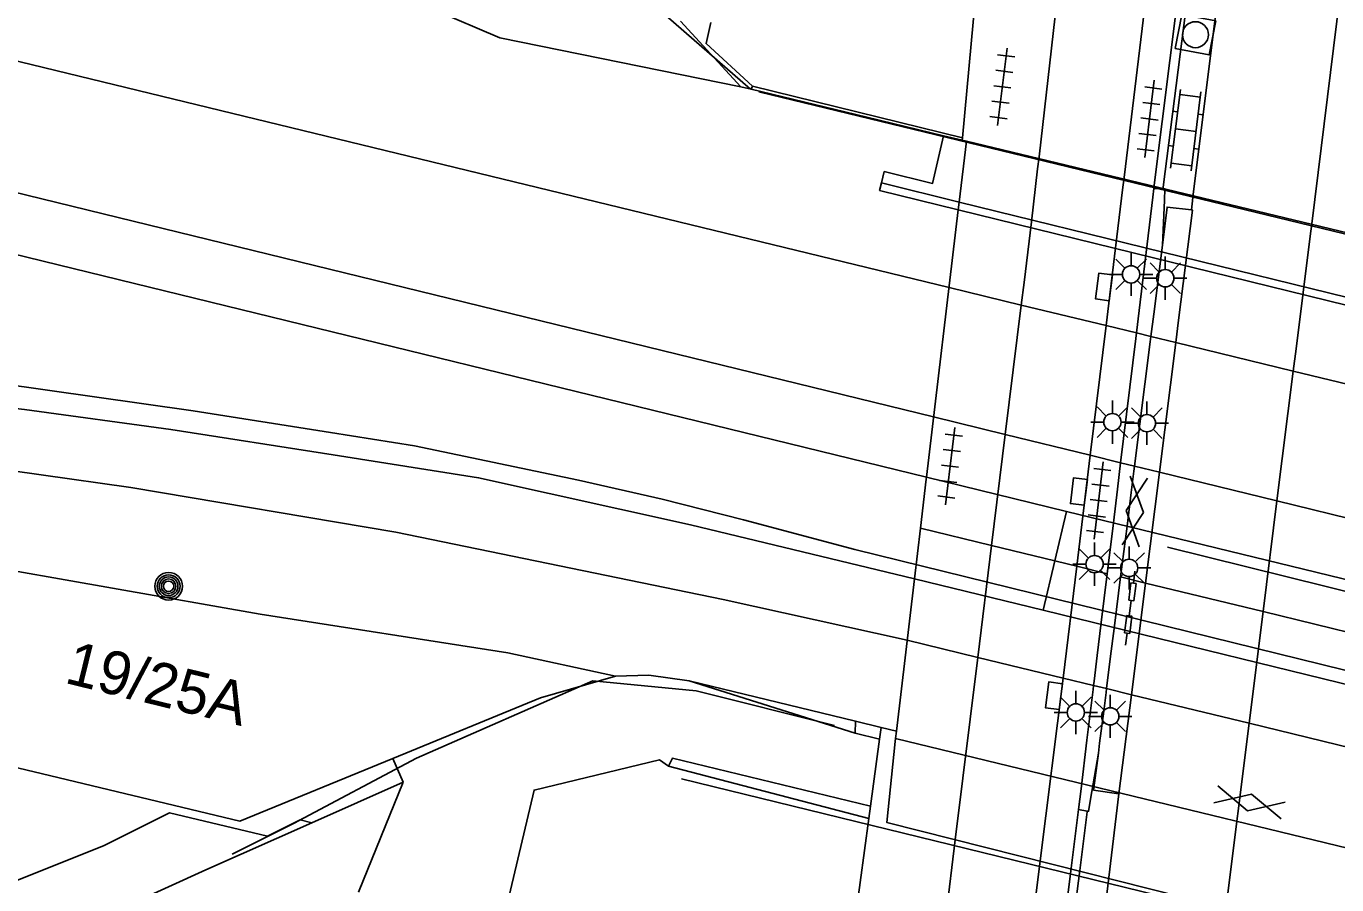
# Model space of a CAD drawing. Extents: x 131000 to 133014, y 396499 to 399001.
# Drawn here: x 131662.22 to 131700.07, y 397388.52 to 397413.33 of the extents above; entities that cross this region are included whole.
import ezdxf

# ---------------------------------------------------------------- set-up
doc = ezdxf.new("R2010")
doc.units = 0
for name, color, linetype in [('gg-afsc-hekwerk', 7, 'Continuous'), ('gg-afsc-muur', 7, 'Continuous'), ('gg-aspt-spoorlijn', 7, 'Continuous'), ('gg-knt-BGT kruinlijn', 7, 'Continuous'), ('gg-knt-bronhoudergrens niveau 01', 7, 'Continuous'), ('gg-knt-verharding', 7, 'Continuous'), ('gg-knt-verharding niveau 01', 7, 'Continuous'), ('gg-knt-verharding nz', 7, 'Continuous'), ('gg-kntw-beschoeiing', 7, 'Continuous'), ('gg-kwrk-kunstwerk', 7, 'Continuous'), ('gg-kwrk-kunstwerk niveau 01', 7, 'Continuous'), ('gt-anno-nummer portaalmast', 7, 'Continuous'), ('gt-grn-afwateringsgoot', 7, 'Continuous'), ('gt-grn-bladgrens', 7, 'Continuous'), ('gt-grn-groengrens', 7, 'Continuous'), ('gt-grn-weggrens', 7, 'Continuous'), ('gt-symb-afwateringsgoot', 7, 'Continuous'), ('gt-symb-gesloten verharding', 7, 'Continuous'), ('gt-symb-klinker verharding', 7, 'Continuous'), ('gt-symb-kolk', 7, 'Continuous'), ('gt-symb-lichtmast', 7, 'Continuous'), ('gt-symb-portaalmast', 7, 'Continuous'), ('gt-symb-rioolschacht', 7, 'Continuous'), ('gt-symb-tegel verharding', 7, 'Continuous'), ('gx-grn-maaiveld', 7, 'Continuous'), ('gx-knt-lijn weginrichtingselement', 7, 'Continuous')]:
    doc.layers.add(name, color=color, linetype=linetype)

# ---------------------------------------------------------------- blocks, each defined once
blk = doc.blocks.new('gt0-TEG1')
at = {"layer": 'gt-symb-tegel verharding'}
for p, q in [((-1.125, 0), (1.125, 0)), ((-0.9, -0.25), (-0.9, 0.25)), ((-0.45, -0.25), (-0.45, 0.25)), ((0, -0.25), (0, 0.25)), ((0.45, -0.25), (0.45, 0.25)), ((0.9, -0.25), (0.9, 0.25))]:
    blk.add_line(p, q, dxfattribs=at)
blk = doc.blocks.new('gt0-KOLK')
at = {"layer": 'gt-symb-kolk'}
blk.add_lwpolyline([(0, 0), (0.375, 0), (0.375, 0.4), (-0.375, 0.4), (-0.375, 0), (0, 0)], dxfattribs=at)
blk = doc.blocks.new('gt0-LMAST')
at = {"layer": 'gt-symb-lichtmast'}
for p, q in [((-0.182, 0.173), (-0.447, 0.438)), ((-0.005, 0.246), (-0.005, 0.621)), ((0.172, 0.173), (0.437, 0.438)), ((-0.255, -0.004), (-0.63, -0.004)), ((-0.182, -0.181), (-0.447, -0.446)), ((-0.005, -0.254), (-0.005, -0.629)), ((0.437, -0.446), (0.172, -0.181)), ((0.245, -0.004), (0.62, -0.004))]:
    blk.add_line(p, q, dxfattribs=at)
blk.add_circle((-0.005, -0.004), 0.25, dxfattribs=at)
blk = doc.blocks.new('gt0-KL1')
at = {"layer": 'gt-symb-klinker verharding'}
for p, q in [((-0.5, 0.3), (-0.5, 0.45)), ((0.5, 0.3), (0.5, 0.45)), ((-1.15, 0.3), (1.15, 0.3)), ((-1, -0.3), (-1, 0.3)), ((0, -0.3), (0, 0.3)), ((1, -0.3), (1, 0.3)), ((-1.15, -0.3), (1.15, -0.3)), ((-0.5, -0.45), (-0.5, -0.3)), ((0.5, -0.45), (0.5, -0.3))]:
    blk.add_line(p, q, dxfattribs=at)
blk = doc.blocks.new('gt0-RS')
at = {"layer": 'gt-symb-rioolschacht'}
blk.add_lwpolyline([(-0.5, -0.5), (0.5, -0.5), (0.5, 0.5), (-0.5, 0.5)], close=True, dxfattribs=at)
blk.add_circle((0, 0), 0.375, dxfattribs=at)
blk = doc.blocks.new('gt0-AFWGT_1')
at = {"layer": 'gt-symb-afwateringsgoot'}
for p, q in [((-1.076, 0), (-0.726, 0)), ((-0.225, 0), (0.225, 0)), ((0.725, 0), (1.075, 0))]:
    blk.add_line(p, q, dxfattribs=at)
for points in [[(-0.726, 0.075), (-0.225, 0.075), (-0.225, -0.075), (-0.726, -0.075)], [(0.225, 0.075), (0.725, 0.075), (0.725, -0.075), (0.225, -0.075)]]:
    blk.add_lwpolyline(points, close=True, dxfattribs=at)
blk = doc.blocks.new('gt0-GESVH1')
at = {"layer": 'gt-symb-gesloten verharding'}
for p, q in [((-0.992, -0.261), (0.008, 0.239)), ((0.008, -0.261), (-0.992, 0.239)), ((0.008, 0.239), (1.008, -0.261)), ((1.008, 0.239), (0.008, -0.261))]:
    blk.add_line(p, q, dxfattribs=at)
blk = doc.blocks.new('gt0-PORTM')
at = {"layer": 'gt-symb-portaalmast'}
for radius in [0.4, 0.33, 0.27, 0.21, 0.15]:
    blk.add_circle((0, 0), radius, dxfattribs=at)

msp = doc.modelspace()

# ---------------------------------------------------------------- linework, layer by layer
at = {"layer": 'gg-afsc-hekwerk'}
for p, q in [((131681.36, 397394.418), (131686.156, 397392.9)), ((131681.36, 397394.418), (131686.167, 397393.246)), ((131686.167, 397393.246), (131686.909, 397393.066)), ((131686.156, 397392.9), (131686.862, 397392.726)), ((131686.909, 397393.066), (131687.346, 397392.959))]:
    msp.add_line(p, q, dxfattribs=at)
for points in [[(131000, 397578.954), (131023.909, 397573.075), (131026.424, 397572.808), (131028.848, 397572.282), (131031.154, 397571.32), (131074.945, 397560.582), (131075.617, 397563.17), (131129.246, 397549.781), (131134.14, 397548.559), (131160.34, 397542.075), (131253.589, 397518.947), (131281.644, 397511.969), (131366.85, 397490.76), (131408.241, 397480.462), (131415.53, 397478.732), (131442.327, 397472.075), (131471.538, 397464.853), (131483.734, 397461.851), (131495.913, 397458.862), (131510.417, 397455.392), (131520.022, 397452.992), (131680.243, 397414.026), (131683.133, 397411.511)], [(131615.544, 397410.102), (131620.261, 397409.009), (131622.612, 397408.496), (131624.978, 397407.98), (131629.886, 397407.06), (131634.678, 397406.22), (131637.064, 397405.839), (131639.453, 397405.498), (131644.286, 397404.898), (131649.239, 397404.372), (131654.019, 397403.86), (131658.97, 397403.278), (131661.391, 397403.013), (131667.033, 397402.217), (131671.003, 397401.595), (131673.429, 397401.203), (131678.166, 397400.215), (131680.583, 397399.662), (131682.932, 397399.07), (131686.144, 397398.212)], [(131611.339, 397404.05), (131668.384, 397390.361), (131672.799, 397392.172)], [(131668.166, 397389.409), (131669.936, 397390.288), (131673.487, 397392.183), (131678.576, 397394.412), (131681.563, 397394.125), (131685.563, 397393.129)], [(131672.799, 397392.172), (131677.071, 397393.925), (131679.238, 397394.55)], [(131679.238, 397394.55), (131680.193, 397394.583), (131681.36, 397394.418)]]:
    msp.add_lwpolyline(points, dxfattribs=at)
at = {"layer": 'gg-afsc-muur'}
for p, q in [((131694.796, 397408.742), (131696.097, 397419.11)), ((131696.38, 397419.146), (131695.051, 397408.68)), ((131694.784, 397408.646), (131694.796, 397408.742)), ((131694.753, 397408.39), (131694.357, 397405.116)), ((131694.784, 397408.646), (131694.753, 397408.39)), ((131695.045, 397408.635), (131694.784, 397408.646)), ((131695.051, 397408.68), (131695.045, 397408.635)), ((131694.357, 397405.116), (131694.278, 397404.468)), ((131694.259, 397404.311), (131693.824, 397400.72)), ((131694.278, 397404.468), (131694.259, 397404.311)), ((131693.824, 397400.72), (131693.732, 397399.958)), ((131693.732, 397399.958), (131693.613, 397398.979)), ((131693.613, 397398.979), (131693.435, 397397.511)), ((131693.435, 397397.511), (131693.264, 397396.101)), ((131693.264, 397396.101), (131693.148, 397395.145)), ((131693.148, 397395.145), (131693.059, 397394.409)), ((131693.059, 397394.409), (131693.043, 397394.279)), ((131693.03, 397394.168), (131692.965, 397393.629)), ((131693.043, 397394.279), (131693.03, 397394.168)), ((131692.965, 397393.629), (131692.852, 397392.699)), ((131692.852, 397392.699), (131692.681, 397391.293)), ((131692.681, 397391.293), (131692.609, 397390.693)), ((131692.609, 397390.693), (131692.397, 397388.998)), ((131692.853, 397390.632), (131692.641, 397388.938)), ((131692.853, 397390.632), (131692.855, 397390.651)), ((131692.641, 397388.938), (131684.58, 397324.435))]:
    msp.add_line(p, q, dxfattribs=at)
msp.add_lwpolyline([(131692.397, 397388.998), (131684.363, 397324.714), (131683.678, 397324.799), (131683.647, 397324.551)], dxfattribs=at)
at = {"layer": 'gg-aspt-spoorlijn'}
for p, q in [((131688.867, 397405.783), (131690.954, 397405.276)), ((131690.954, 397405.276), (131693.404, 397404.681)), ((131693.404, 397404.681), (131694.278, 397404.468)), ((131694.278, 397404.468), (131694.7, 397404.366)), ((131694.7, 397404.366), (131695.417, 397404.192)), ((131695.417, 397404.192), (131698.809, 397403.367)), ((131698.809, 397403.367), (131702.237, 397402.535)), ((131688.423, 397402.041), (131690.492, 397401.535)), ((131690.492, 397401.535), (131692.947, 397400.934)), ((131692.947, 397400.934), (131693.824, 397400.72)), ((131693.824, 397400.72), (131694.227, 397400.621)), ((131694.227, 397400.621), (131694.945, 397400.445)), ((131694.945, 397400.445), (131698.338, 397399.615)), ((131698.338, 397399.615), (131701.77, 397398.775)), ((131687.658, 397395.589), (131689.697, 397395.093)), ((131689.697, 397395.093), (131692.162, 397394.494)), ((131692.162, 397394.494), (131693.043, 397394.279)), ((131693.043, 397394.279), (131693.416, 397394.189)), ((131693.416, 397394.189), (131694.136, 397394.014)), ((131694.136, 397394.014), (131697.533, 397393.187)), ((131697.533, 397393.187), (131700.973, 397392.351))]:
    msp.add_line(p, q, dxfattribs=at)
for points in [[(131000, 397574.063), (131015.158, 397570.378), (131155.057, 397536.094), (131235.084, 397516.609), (131444.076, 397465.45), (131583.687, 397431.335), (131688.867, 397405.783)], [(131000, 397570.437), (131010.144, 397567.969), (131268.679, 397504.671), (131357.363, 397483.039), (131688.423, 397402.041)], [(131687.658, 397395.589), (131682.349, 397396.764), (131672.888, 397398.708), (131665.233, 397400.005), (131657.459, 397401.104), (131644.632, 397402.561), (131637.954, 397403.425), (131633.845, 397404.09), (131626.094, 397405.478), (131616.553, 397407.522), (131608.371, 397409.522), (131568.382, 397419.291), (131463.389, 397444.974), (131387.923, 397463.502)]]:
    msp.add_lwpolyline(points, dxfattribs=at)
at = {"layer": 'gg-knt-BGT kruinlijn'}
msp.add_lwpolyline([(131683.19, 397411.6), (131681.85, 397412.83), (131681.991, 397413.439)], dxfattribs=at)
at = {"layer": 'gg-knt-bronhoudergrens niveau 01'}
msp.add_line((131718.733, 397402.927), (131689.368, 397410.01), dxfattribs=at)
at = {"layer": 'gg-knt-verharding'}
for p, q in [((131695.921, 397408.466), (131697.257, 397419.259)), ((131690.004, 397418.332), (131689.259, 397410.106)), ((131686.156, 397392.9), (131686.167, 397393.246)), ((131673.101, 397391.49), (131672.799, 397392.172)), ((131670.462, 397390.315), (131673.101, 397391.49)), ((131686.552, 397390.436), (131685.953, 397386.015)), ((131688.148, 397382.542), (131689.046, 397389.823)), ((131690.636, 397382.235), (131691.503, 397389.218))]:
    msp.add_line(p, q, dxfattribs=at)
for points in [[(131694.962, 397418.965), (131694.818, 397416.652), (131694.513, 397413.827), (131693.925, 397408.957)], [(131691.466, 397409.562), (131692.342, 397417.211), (131692.442, 397418.643)], [(131676.17, 397387.236), (131675.941, 397387.271), (131676.883, 397391.258), (131680.501, 397392.13), (131680.77, 397391.95)], [(131651.976, 397382.653), (131656.552, 397384.318), (131660.374, 397385.875), (131663.959, 397387.385), (131667.407, 397388.955), (131670.462, 397390.315)], [(131693.483, 397388.731), (131693.07, 397385.295), (131692.473, 397380.737), (131690.096, 397361.391), (131687.567, 397341.018), (131685.533, 397324.317)]]:
    msp.add_lwpolyline(points, dxfattribs=at)
at = {"layer": 'gg-knt-verharding niveau 01'}
for p, q in [((131689.16, 397408.251), (131689.368, 397410.01)), ((131688.217, 397400.3), (131689.133, 397408.027)), ((131689.133, 397408.027), (131689.16, 397408.251)), ((131689.133, 397408.027), (131718.491, 397400.804)), ((131689.16, 397408.251), (131718.517, 397401.028)), ((131688.217, 397400.3), (131692.263, 397399.311)), ((131691.587, 397396.455), (131692.263, 397399.311)), ((131692.263, 397399.311), (131717.617, 397393.116)), ((131687.868, 397397.365), (131691.587, 397396.455))]:
    msp.add_line(p, q, dxfattribs=at)
for points in [[(131688.217, 397400.3), (131688.211, 397400.246), (131688.041, 397398.823)], [(131691.587, 397396.455), (131702.513, 397393.782), (131717.279, 397390.145)]]:
    msp.add_lwpolyline(points, dxfattribs=at)
at = {"layer": 'gg-knt-verharding nz'}
for p, q in [((131700.84, 397419.717), (131699.343, 397407.624)), ((131689.259, 397410.106), (131689.249, 397410.039)), ((131691.426, 397409.212), (131691.466, 397409.562)), ((131693.882, 397408.605), (131693.925, 397408.957)), ((131693.483, 397405.329), (131693.882, 397408.605)), ((131695.877, 397408.113), (131695.921, 397408.466)), ((131695.033, 397407.006), (131695.086, 397408.308)), ((131695.866, 397408.026), (131695.877, 397408.113)), ((131699.343, 397407.624), (131699.298, 397407.267)), ((131699.298, 397407.267), (131698.889, 397404.007)), ((131694.781, 397405.012), (131695.033, 397407.006)), ((131690.954, 397405.276), (131691.034, 397405.928)), ((131693.404, 397404.681), (131693.483, 397405.329)), ((131690.492, 397401.535), (131690.954, 397405.276)), ((131694.7, 397404.366), (131694.781, 397405.012)), ((131692.947, 397400.934), (131693.404, 397404.681)), ((131694.227, 397400.621), (131694.68, 397404.208)), ((131694.68, 397404.208), (131694.7, 397404.366)), ((131698.889, 397404.007), (131698.809, 397403.367)), ((131698.338, 397399.615), (131698.809, 397403.367)), ((131690.492, 397401.535), (131690.096, 397398.323)), ((131692.947, 397400.934), (131692.556, 397397.725)), ((131694.132, 397399.86), (131694.208, 397400.47)), ((131694.208, 397400.47), (131694.227, 397400.621)), ((131694.008, 397398.882), (131694.132, 397399.86)), ((131698.338, 397399.615), (131697.937, 397396.416)), ((131693.823, 397397.416), (131694.008, 397398.882)), ((131690.096, 397398.323), (131689.697, 397395.093)), ((131692.556, 397397.725), (131692.162, 397394.494)), ((131693.646, 397396.009), (131693.823, 397397.416)), ((131697.937, 397396.416), (131697.533, 397393.187)), ((131693.525, 397395.053), (131693.646, 397396.009)), ((131689.697, 397395.093), (131689.046, 397389.823)), ((131693.416, 397394.189), (131693.525, 397395.053)), ((131692.162, 397394.494), (131691.503, 397389.218)), ((131693.334, 397393.539), (131693.402, 397394.078)), ((131693.402, 397394.078), (131693.416, 397394.189)), ((131693.217, 397392.611), (131693.334, 397393.539)), ((131686.909, 397393.066), (131686.862, 397392.726)), ((131693.181, 397392.326), (131693.217, 397392.611)), ((131693.181, 397392.326), (131692.996, 397391.216)), ((131693.775, 397391.148), (131693.483, 397388.731)), ((131686.6, 397390.792), (131686.552, 397390.436)), ((131692.855, 397390.651), (131692.609, 397390.693))]:
    msp.add_line(p, q, dxfattribs=at)
for points in [[(131691.034, 397405.928), (131691.251, 397407.683), (131691.426, 397409.212)], [(131695.086, 397408.308), (131695.099, 397408.633), (131695.045, 397408.635)], [(131689.014, 397323.892), (131689.015, 397323.899), (131696.869, 397387.898), (131697.533, 397393.187)], [(131692.996, 397391.216), (131692.9, 397390.644), (131692.855, 397390.651)]]:
    msp.add_lwpolyline(points, dxfattribs=at)
at = {"layer": 'gg-kntw-beschoeiing'}
for p, q in [((131686.144, 397398.212), (131717.324, 397390.534)), ((131695.174, 397398.278), (131717.574, 397392.739))]:
    msp.add_line(p, q, dxfattribs=at)
at = {"layer": 'gg-kwrk-kunstwerk'}
for p, q in [((131683.19, 397411.6), (131683.154, 397411.51)), ((131689.259, 397410.106), (131683.19, 397411.6)), ((131680.77, 397391.95), (131686.552, 397390.436))]:
    msp.add_line(p, q, dxfattribs=at)
msp.add_lwpolyline([(131686.6, 397390.792), (131680.88, 397392.18), (131680.77, 397391.95)], dxfattribs=at)
at = {"layer": 'gg-kwrk-kunstwerk niveau 01'}
for p, q in [((131688.041, 397398.823), (131687.868, 397397.365)), ((131687.868, 397397.361), (131687.346, 397392.959)), ((131687.868, 397397.365), (131687.868, 397397.361)), ((131687.346, 397392.959), (131687.323, 397392.744)), ((131687.323, 397392.744), (131687.314, 397392.658))]:
    msp.add_line(p, q, dxfattribs=at)
for points in [[(131687.314, 397392.658), (131687.072, 397390.317), (131711.775, 397384.078), (131716.459, 397382.936)], [(131687.323, 397392.744), (131706.6, 397388.063), (131716.763, 397385.611)]]:
    msp.add_lwpolyline(points, dxfattribs=at)
at = {"layer": 'gt-grn-afwateringsgoot'}
for p, q in [((131695.498, 397404.837), (131695.417, 397404.192)), ((131694.945, 397400.445), (131695.417, 397404.192)), ((131694.945, 397400.445), (131694.542, 397397.242)), ((131694.542, 397397.242), (131694.136, 397394.014)), ((131693.775, 397391.148), (131694.136, 397394.014))]:
    msp.add_line(p, q, dxfattribs=at)
for points in [[(131695.033, 397407.006), (131695.163, 397408.104), (131695.866, 397408.026)], [(131695.866, 397408.026), (131695.899, 397408.022), (131695.498, 397404.837)], [(131693.775, 397391.148), (131693.043, 397391.26), (131693.181, 397392.326)]]:
    msp.add_lwpolyline(points, dxfattribs=at)
at = {"layer": 'gt-grn-bladgrens'}
msp.add_line((131688.712, 397410.168), (131689.249, 397410.039), dxfattribs=at)
msp.add_lwpolyline([(131688.712, 397410.168), (131686.496, 397410.703), (131683.154, 397411.51)], dxfattribs=at)
at = {"layer": 'gt-grn-groengrens'}
msp.add_lwpolyline([(131655.315, 397385.992), (131664.444, 397389.643), (131666.351, 397390.597), (131669.179, 397389.927), (131670.129, 397390.396), (131670.462, 397390.315)], dxfattribs=at)
at = {"layer": 'gt-grn-weggrens'}
for p, q in [((131688.041, 397398.823), (131690.096, 397398.323)), ((131690.096, 397398.323), (131692.556, 397397.725)), ((131692.556, 397397.725), (131693.435, 397397.511)), ((131693.823, 397397.416), (131694.542, 397397.242)), ((131694.542, 397397.242), (131697.937, 397396.416)), ((131697.937, 397396.416), (131701.374, 397395.58)), ((131671.813, 397388.31), (131673.101, 397391.49))]:
    msp.add_line(p, q, dxfattribs=at)
at = {"layer": 'gx-grn-maaiveld'}
for p, q in [((131688.217, 397400.3), (131437.578, 397461.66)), ((131682.853, 397411.583), (131681.112, 397413.478)), ((131682.853, 397411.583), (131683.154, 397411.51)), ((131689.368, 397410.01), (131689.249, 397410.039)), ((131686.915, 397408.804), (131689.16, 397408.251)), ((131686.862, 397392.726), (131686.6, 397390.792))]:
    msp.add_line(p, q, dxfattribs=at)
for points in [[(131682.853, 397411.583), (131675.89, 397412.997), (131673.993, 397413.808), (131671.325, 397414.781), (131661.869, 397416.605), (131649.111, 397419.194), (131621.772, 397426.153), (131618.257, 397427.44), (131614.683, 397428.291)], [(131686.915, 397408.804), (131686.998, 397409.131), (131688.391, 397408.789), (131688.712, 397410.168)], [(131687.868, 397397.361), (131681.398, 397398.923), (131675.278, 397400.285), (131671.085, 397400.947), (131666.392, 397401.676), (131662.163, 397402.261), (131656.627, 397402.899), (131648.977, 397403.767), (131643.597, 397404.369), (131639.564, 397404.863), (131637.913, 397405.107), (131634.835, 397405.568), (131631.419, 397406.146), (131627.841, 397406.809), (131625.022, 397407.333), (131619.998, 397408.423), (131614.203, 397409.767)], [(131689.133, 397408.027), (131686.861, 397408.586), (131686.915, 397408.804)], [(131679.238, 397394.55), (131676.127, 397395.222), (131668.97, 397396.346), (131660.428, 397397.84), (131659.777, 397397.154), (131657.982, 397397.37), (131657.608, 397398.069), (131648.428, 397399.322), (131639.042, 397400.19), (131638.175, 397399.334), (131635.241, 397399.708), (131634.114, 397401.057), (131618.078, 397404.31)]]:
    msp.add_lwpolyline(points, dxfattribs=at)
at = {"layer": 'gx-knt-lijn weginrichtingselement'}
for p, q in [((131683.371, 397411.44), (131725.935, 397401.109)), ((131681.137, 397391.58), (131709.863, 397384.561))]:
    msp.add_line(p, q, dxfattribs=at)

# ---------------------------------------------------------------- block references
at = {"layer": 'gt-symb-afwateringsgoot', "xscale": 0.9999217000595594, "yscale": 0.9999217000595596, "rotation": 82.84033593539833}
msp.add_blockref('gt0-AFWGT_1', (131694.103, 397396.516), dxfattribs=at)
at = {"layer": 'gt-symb-gesloten verharding'}
for p, rotation in [((131694.22, 397399.305), 83.16632765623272), ((131697.538, 397390.914), -13.535856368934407)]:
    msp.add_blockref('gt0-GESVH1', p, dxfattribs=dict(at, rotation=rotation))
at = {"layer": 'gt-symb-klinker verharding', "rotation": 82.81812146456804}
msp.add_blockref('gt0-KL1', (131695.703, 397410.33), dxfattribs=at)
at = {"layer": 'gt-symb-kolk'}
for p, rotation in [((131693.541, 397405.774), 82.99574075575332), ((131692.817, 397399.862), 83.05258934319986), ((131692.097, 397393.96), 82.87498365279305)]:
    msp.add_blockref('gt0-KOLK', p, dxfattribs=dict(at, rotation=rotation))
at = {"layer": 'gt-symb-lichtmast'}
for p in [(131694.131, 397406.166), (131695.119, 397406.054), (131693.591, 397401.895), (131694.589, 397401.865), (131693.075, 397397.791), (131694.075, 397397.681), (131692.535, 397393.505), (131693.53, 397393.393)]:
    msp.add_blockref('gt0-LMAST', p, dxfattribs=at)
at = {"layer": 'gt-symb-portaalmast'}
msp.add_blockref('gt0-PORTM', (131666.328, 397397.149), dxfattribs=at)
at = {"layer": 'gt-symb-rioolschacht', "rotation": -10.894182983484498}
msp.add_blockref('gt0-RS', (131695.983, 397413.088), dxfattribs=at)
at = {"layer": 'gt-symb-tegel verharding'}
for p, rotation in [((131690.408, 397411.583), 82.93185994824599), ((131694.657, 397410.653), 82.9318599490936), ((131688.897, 397400.622), 83.16632765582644), ((131693.189, 397399.626), 83.16632765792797)]:
    msp.add_blockref('gt0-TEG1', p, dxfattribs=dict(at, rotation=rotation))

# ---------------------------------------------------------------- texts
at = {"layer": 'gt-anno-nummer portaalmast'}
msp.add_text('19/25A', height=1.25, rotation=346.2279, dxfattribs=at).set_placement((131663.287, 397394.365))

doc.saveas('drawing.dxf')
